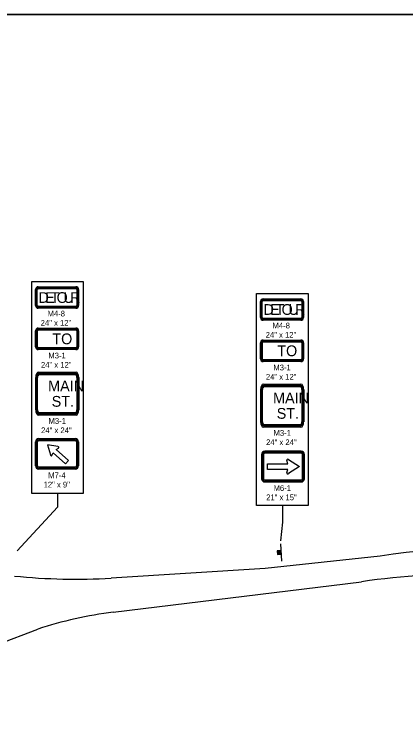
# Model space of a CAD drawing. Extents: x 10133 to 81668, y 6132 to 11018.
# Drawn here: x 10970 to 11517, y 8934 to 9944 of the extents above; entities that cross this region are included whole.
import ezdxf

# ---------------------------------------------------------------- set-up
doc = ezdxf.new("R2010")
doc.units = 0
for name, color, linetype in [('dsnTextFinalPlan', 7, 'Continuous'), ('Level 10', 7, 'Continuous'), ('Level 5', 7, 'Continuous'), ('SheetBorder', 7, 'Continuous'), ('SheetText', 7, 'Continuous')]:
    doc.layers.add(name, color=color, linetype=linetype)

msp = doc.modelspace()

# ---------------------------------------------------------------- linework, layer by layer
at = {"layer": 'dsnTextFinalPlan'}
for p, q in [((10999.7, 9313.4), (10999.7, 9347.2)), ((11004.3, 9351.7), (11055.3, 9351.7)), ((11059.8, 9347.2), (11059.8, 9313.4)), ((11055.3, 9308.8), (11004.3, 9308.8)), ((11342.2, 9204.5), (11343.8, 9180.6)), ((11338.2, 9194.7), (11338.5, 9189.8)), ((11338.8, 9189.9), (11338.5, 9194.7)), ((11338.7, 9194.7), (11339, 9189.9)), ((11339.3, 9189.9), (11338.9, 9194.8)), ((11339.1, 9194.8), (11339.5, 9189.9)), ((11339.8, 9189.9), (11339.5, 9194.8)), ((11339.7, 9194.8), (11340, 9190)), ((11340.4, 9190), (11340.1, 9194.8)), ((11340.4, 9194.9), (11340.7, 9190)), ((11341, 9190), (11340.7, 9194.9)), ((11340.9, 9194.9), (11341.2, 9190)), ((11341.4, 9190.1), (11341.1, 9194.9)), ((11341.4, 9194.9), (11341.7, 9190.1)), ((11341.9, 9190.1), (11341.6, 9194.9)), ((11341.8, 9195), (11342.1, 9190.1)), ((11342.3, 9190.1), (11342, 9195)), ((11342.2, 9195), (11342.6, 9190.1)), ((11342.8, 9190.1), (11342.5, 9195)), ((11108.6, 9109), (11455.8, 9151.7)), ((10879.5, 9038.3), (11002.9, 9085.5))]:
    msp.add_line(p, q, dxfattribs=at)
for points in [[(10994.4, 9571.2), (11066.4, 9571.2), (11066.4, 9275.1), (10994.4, 9275.1)], [(10994.4, 9571.2), (11066.4, 9571.2), (11066.4, 9275.1), (10994.4, 9275.1)], [(11309, 9554.4), (11381.1, 9554.4), (11381.1, 9258.3), (11309, 9258.3)], [(11309, 9554.4), (11381.1, 9554.4), (11381.1, 9258.3), (11309, 9258.3)], [(11343.1, 9190.2), (11342.7, 9195.1), (11337.8, 9194.7), (11338.2, 9189.8)]]:
    msp.add_lwpolyline(points, close=True, dxfattribs=at)
for points in [[(11031, 9340.6), (11016.6, 9342.7), (11020.5, 9328.7)], [(11022.7, 9328.2), (11024.3, 9331.7), (11041.7, 9316.4), (11045.8, 9321.1), (11028.5, 9336.4), (11031.8, 9338.4)], [(11030.4, 9275.1), (11030.4, 9255.6), (10974.1, 9194.9)], [(11345, 9258.3), (11345, 9234.7), (11342.4, 9208.7)], [(11481.7, 9187.4), (11321, 9170), (11105.8, 9156.6)]]:
    msp.add_lwpolyline(points, dxfattribs=at)
for centre, radius, start, end in [((11004.3, 9347.2), 4.58, 90, 180), ((11055.3, 9347.2), 4.58, 0, 90), ((11047.5, 9455.4), 116, 261.8049, 261.9654), ((11031.2, 9339.4), 1.16, 302.6073, 81.9654), ((10908.7, 9297.8), 116, 15.2659, 15.4333), ((11021.7, 9328.7), 1.14, 195.2659, 334.5454), ((11004.3, 9313.4), 4.58, 180, 270), ((11055.3, 9313.4), 4.58, 270, 0), ((11625.5, 8266), 932.6, 80.7356, 98.8682), ((11618.9, 7976.3), 1186.7, 81.0032, 97.8988), ((11056.8, 10017.6), 862.4, 264.2445, 273.255), ((11172.1, 8574), 538.7, 96.7772, 108.3032)]:
    msp.add_arc(centre, radius, start, end, dxfattribs=at)
at = {"layer": 'Level 10'}
for p, q in [((10999.8, 9537.4), (10999.8, 9559.9)), ((11000.7, 9559.9), (11002.3, 9559.9)), ((11003.6, 9563.7), (11056.2, 9563.7)), ((11003.6, 9561.2), (11003.6, 9562.7)), ((11056.2, 9562.7), (11056.2, 9561.2)), ((11057.4, 9559.9), (11059, 9559.9)), ((11059.9, 9559.9), (11059.9, 9537.4)), ((11318.2, 9546.9), (11370.8, 9546.9)), ((11318.2, 9544.4), (11318.2, 9546)), ((11370.8, 9546), (11370.8, 9544.4)), ((11002.3, 9537.4), (11000.7, 9537.4)), ((11003.6, 9534.5), (11003.6, 9536.1)), ((11056.2, 9536.1), (11056.2, 9534.5)), ((11059, 9537.4), (11057.4, 9537.4)), ((11314.4, 9520.6), (11314.4, 9543.1)), ((11315.4, 9543.1), (11316.9, 9543.1)), ((11372.1, 9543.1), (11373.6, 9543.1)), ((11374.6, 9543.1), (11374.6, 9520.6)), ((11056.2, 9533.6), (11003.6, 9533.6)), ((11316.9, 9520.6), (11315.4, 9520.6)), ((11318.2, 9517.8), (11318.2, 9519.3)), ((11370.8, 9516.8), (11318.2, 9516.8)), ((11370.8, 9519.3), (11370.8, 9517.8)), ((11373.6, 9520.6), (11372.1, 9520.6)), ((11003.6, 9506), (11056.2, 9506)), ((11003.6, 9503.5), (11003.6, 9505)), ((11056.2, 9505), (11056.2, 9503.5)), ((10999.8, 9479.7), (10999.8, 9502.2)), ((11000.8, 9502.2), (11002.4, 9502.2)), ((11057.5, 9502.2), (11059, 9502.2)), ((11060, 9502.2), (11060, 9479.7)), ((11314.5, 9462.9), (11314.5, 9485.5)), ((11315.4, 9485.5), (11317, 9485.5)), ((11318.2, 9489.2), (11370.9, 9489.2)), ((11318.2, 9486.7), (11318.2, 9488.3)), ((11370.9, 9488.3), (11370.9, 9486.7)), ((11372.1, 9485.5), (11373.7, 9485.5)), ((11374.6, 9485.5), (11374.6, 9462.9)), ((11002.4, 9479.7), (11000.8, 9479.7)), ((11003.6, 9476.9), (11003.6, 9478.4)), ((11056.2, 9475.9), (11003.6, 9475.9)), ((11056.2, 9478.4), (11056.2, 9476.9)), ((11059, 9479.7), (11057.5, 9479.7)), ((11317, 9462.9), (11315.4, 9462.9)), ((11318.2, 9460.1), (11318.2, 9461.7)), ((11370.9, 9459.2), (11318.2, 9459.2)), ((11370.9, 9461.7), (11370.9, 9460.1)), ((11373.7, 9462.9), (11372.1, 9462.9)), ((11003.8, 9444.4), (11056.4, 9444.4)), ((11000, 9391.8), (11000, 9436.9)), ((11001, 9436.9), (11002.5, 9436.9)), ((11003.8, 9439.4), (11003.8, 9442.5)), ((11056.4, 9442.5), (11056.4, 9441)), ((11057.7, 9436.9), (11059.2, 9436.9)), ((11060.2, 9436.9), (11060.2, 9391.8)), ((11318.4, 9427.6), (11371, 9427.6)), ((11318.4, 9422.6), (11318.4, 9425.8)), ((11371, 9425.8), (11371, 9424.2)), ((11314.7, 9375), (11314.7, 9420.1)), ((11315.6, 9420.1), (11317.2, 9420.1)), ((11372.3, 9420.1), (11373.9, 9420.1)), ((11374.8, 9420.1), (11374.8, 9375)), ((11002.5, 9391.8), (11001, 9391.8)), ((11003.8, 9386.1), (11003.8, 9389.3)), ((11056.4, 9384.3), (11003.8, 9384.3)), ((11056.4, 9387.7), (11056.4, 9386.1)), ((11059.2, 9391.8), (11057.7, 9391.8)), ((11317.2, 9375), (11315.6, 9375)), ((11373.9, 9375), (11372.3, 9375)), ((11318.4, 9369.4), (11318.4, 9372.5)), ((11371, 9367.5), (11318.4, 9367.5)), ((11371, 9370.9), (11371, 9369.4)), ((11000.9, 9313.4), (11000.9, 9347.2)), ((11002.6, 9313.4), (11002.6, 9347.2)), ((11004.3, 9350.6), (11055.3, 9350.6)), ((11004.3, 9348.9), (11055.3, 9348.9)), ((11057, 9347.2), (11057, 9313.4)), ((11058.7, 9347.2), (11058.7, 9313.4)), ((11371.3, 9334), (11320.4, 9334)), ((11371.3, 9332.8), (11320.4, 9332.8)), ((11315.8, 9329.4), (11315.8, 9295.6)), ((11316.9, 9329.4), (11316.9, 9295.6)), ((11318.6, 9329.4), (11318.6, 9295.6)), ((11371.3, 9331.1), (11320.4, 9331.1)), ((11373, 9295.6), (11373, 9329.4)), ((11374.8, 9295.6), (11374.8, 9329.4)), ((11375.9, 9295.6), (11375.9, 9329.4)), ((11055.3, 9311.6), (11004.3, 9311.6)), ((11055.3, 9309.9), (11004.3, 9309.9)), ((11320.4, 9293.9), (11371.3, 9293.9)), ((11320.4, 9292.2), (11371.3, 9292.2)), ((11320.4, 9291), (11371.3, 9291))]:
    msp.add_line(p, q, dxfattribs=at)
for points in [[(11000.7, 9559.9), (11000.7, 9537.4), (11002.3, 9537.4), (11002.3, 9559.9), (11000.7, 9559.9)], [(11056.2, 9562.7), (11003.6, 9562.7), (11003.6, 9561.2), (11056.2, 9561.2), (11056.2, 9562.7)], [(11059, 9537.4), (11059, 9559.9), (11057.4, 9559.9), (11057.4, 9537.4), (11059, 9537.4)], [(11370.8, 9546), (11318.2, 9546), (11318.2, 9544.4), (11370.8, 9544.4), (11370.8, 9546)], [(11003.6, 9534.5), (11056.2, 9534.5), (11056.2, 9536.1), (11003.6, 9536.1), (11003.6, 9534.5)], [(11315.4, 9543.1), (11315.4, 9520.6), (11316.9, 9520.6), (11316.9, 9543.1), (11315.4, 9543.1)], [(11373.6, 9520.6), (11373.6, 9543.1), (11372.1, 9543.1), (11372.1, 9520.6), (11373.6, 9520.6)], [(11318.2, 9517.8), (11370.8, 9517.8), (11370.8, 9519.3), (11318.2, 9519.3), (11318.2, 9517.8)], [(11056.2, 9505), (11003.6, 9505), (11003.6, 9503.5), (11056.2, 9503.5), (11056.2, 9505)], [(11000.8, 9502.2), (11000.8, 9479.7), (11002.4, 9479.7), (11002.4, 9502.2), (11000.8, 9502.2)], [(11059, 9479.7), (11059, 9502.2), (11057.5, 9502.2), (11057.5, 9479.7), (11059, 9479.7)], [(11315.4, 9485.5), (11315.4, 9462.9), (11317, 9462.9), (11317, 9485.5), (11315.4, 9485.5)], [(11370.9, 9488.3), (11318.2, 9488.3), (11318.2, 9486.7), (11370.9, 9486.7), (11370.9, 9488.3)], [(11373.7, 9462.9), (11373.7, 9485.5), (11372.1, 9485.5), (11372.1, 9462.9), (11373.7, 9462.9)], [(11003.6, 9476.9), (11056.2, 9476.9), (11056.2, 9478.4), (11003.6, 9478.4), (11003.6, 9476.9)], [(11318.2, 9460.1), (11370.9, 9460.1), (11370.9, 9461.7), (11318.2, 9461.7), (11318.2, 9460.1)], [(11001, 9436.9), (11001, 9391.8), (11002.5, 9391.8), (11002.5, 9436.9), (11001, 9436.9)], [(11056.4, 9442.5), (11003.8, 9442.5), (11003.8, 9441), (11056.4, 9441), (11056.4, 9442.5)], [(11059.2, 9391.8), (11059.2, 9436.9), (11057.7, 9436.9), (11057.7, 9391.8), (11059.2, 9391.8)], [(11371, 9425.8), (11318.4, 9425.8), (11318.4, 9424.2), (11371, 9424.2), (11371, 9425.8)], [(11315.6, 9420.1), (11315.6, 9375), (11317.2, 9375), (11317.2, 9420.1), (11315.6, 9420.1)], [(11373.9, 9375), (11373.9, 9420.1), (11372.3, 9420.1), (11372.3, 9375), (11373.9, 9375)], [(11003.8, 9386.1), (11056.4, 9386.1), (11056.4, 9387.7), (11003.8, 9387.7), (11003.8, 9386.1)], [(11318.4, 9369.4), (11371, 9369.4), (11371, 9370.9), (11318.4, 9370.9), (11318.4, 9369.4)]]:
    msp.add_lwpolyline(points, close=True, dxfattribs=at)
for points in [[(11353.8, 9322.3), (11368.8, 9312.5), (11353.8, 9302.7)], [(11351.3, 9304), (11352.7, 9308.6), (11324.1, 9308.6), (11324.1, 9316.4), (11352.7, 9316.4), (11351.3, 9321)]]:
    msp.add_lwpolyline(points, dxfattribs=at)
for centre, radius, start, end in [((11003.6, 9559.9), 3.76, 90, 180), ((11003.6, 9559.9), 2.82, 90.0002, 179.9998), ((11003.6, 9559.9), 1.25, 90.0002, 179.9998), ((11056.2, 9559.9), 3.76, 0, 90), ((11056.2, 9559.9), 2.82, 0, 90.0002), ((11056.2, 9559.9), 1.25, 0, 90.0002), ((11318.2, 9543.1), 3.76, 90, 180), ((11318.2, 9543.1), 2.82, 90.0002, 179.9998), ((11370.8, 9543.1), 3.76, 0, 90), ((11370.8, 9543.1), 2.82, 0, 90.0002), ((11003.6, 9537.4), 3.76, 180, 270), ((11003.6, 9537.4), 2.82, 179.9998, 270.0001), ((11003.6, 9537.4), 1.25, 179.9998, 270.0001), ((11056.2, 9537.4), 2.82, 270.0001, 0.0003), ((11056.2, 9537.4), 1.25, 270.0001, 0.0003), ((11056.2, 9537.4), 3.76, 270, 359.9911), ((11318.2, 9543.1), 1.25, 90.0002, 179.9998), ((11370.8, 9543.1), 1.25, 0, 90.0002), ((11318.2, 9520.6), 3.76, 180, 270), ((11318.2, 9520.6), 2.82, 179.9998, 270.0001), ((11318.2, 9520.6), 1.25, 179.9998, 270.0001), ((11370.8, 9520.6), 2.82, 270.0001, 0.0003), ((11370.8, 9520.6), 1.25, 270.0001, 0.0003), ((11370.8, 9520.6), 3.76, 270, 359.9911), ((11003.6, 9502.2), 3.76, 90, 180), ((11003.6, 9502.2), 2.82, 90.0002, 179.9998), ((11056.2, 9502.2), 3.76, 0, 90), ((11056.2, 9502.2), 2.82, 0, 90.0002), ((11003.6, 9502.2), 1.25, 90.0002, 179.9998), ((11056.2, 9502.2), 1.25, 0, 90.0002), ((11318.2, 9485.5), 3.76, 90, 180), ((11318.2, 9485.5), 2.82, 90.0002, 179.9998), ((11318.2, 9485.5), 1.25, 90.0002, 179.9998), ((11370.9, 9485.5), 3.76, 0, 90), ((11370.9, 9485.5), 2.82, 0, 90.0002), ((11370.9, 9485.5), 1.25, 0, 90.0002), ((11003.6, 9479.7), 3.76, 180, 270), ((11003.6, 9479.7), 2.82, 179.9998, 270.0001), ((11003.6, 9479.7), 1.25, 179.9998, 270.0001), ((11056.2, 9479.7), 2.82, 270.0001, 0.0003), ((11056.2, 9479.7), 1.25, 270.0001, 0.0003), ((11056.2, 9479.7), 3.76, 270, 359.9911), ((11318.2, 9462.9), 3.76, 180, 270), ((11318.2, 9462.9), 2.82, 179.9998, 270.0001), ((11318.2, 9462.9), 1.25, 179.9998, 270.0001), ((11370.9, 9462.9), 2.82, 270.0001, 0.0003), ((11370.9, 9462.9), 1.25, 270.0001, 0.0003), ((11370.9, 9462.9), 3.76, 270, 359.9911), ((11004.3, 9347.2), 3.44, 90, 180), ((11004.3, 9347.2), 1.72, 90, 180), ((11055.3, 9347.2), 3.44, 0, 90), ((11055.3, 9347.2), 1.72, 0, 90), ((11320.4, 9329.4), 4.58, 90, 180), ((11320.4, 9329.4), 3.44, 90, 180), ((11371.3, 9329.4), 4.58, 360, 90), ((11371.3, 9329.4), 3.44, 0, 90), ((11320.4, 9329.4), 1.72, 90, 180), ((11352.6, 9321.3), 1.43, 56.6109, 195.9691), ((11432.2, 9442.1), 143.2, 236.6109, 236.7714), ((11371.3, 9329.4), 1.72, 0, 90), ((11004.3, 9313.4), 3.44, 180, 270), ((11004.3, 9313.4), 1.72, 180, 270), ((11055.3, 9313.4), 3.44, 270, 0), ((11055.3, 9313.4), 1.72, 270, 0), ((11352.6, 9303.7), 1.4, 164.0309, 303.3104), ((11432, 9182.8), 143.2, 123.143, 123.3104), ((11320.4, 9295.6), 4.58, 180, 270), ((11320.4, 9295.6), 3.44, 180, 270), ((11320.4, 9295.6), 1.72, 180, 270), ((11371.3, 9295.6), 4.58, 270, 0), ((11371.3, 9295.6), 3.44, 270, 360), ((11371.3, 9295.6), 1.72, 270, 0)]:
    msp.add_arc(centre, radius, start, end, dxfattribs=at)
for centre, major_axis, ratio, start_param, end_param in [((11003.8, 9436.9), (0, 7.52), 0.5, 6.283185, 7.853982), ((11056.4, 9436.9), (0, 7.52), 0.5, 4.712389, 6.283185), ((11003.8, 9436.9), (0, 5.64), 0.5, 0.000004, 1.570794), ((11003.8, 9436.9), (0, 4.07), 0.307692, 0.000004, 1.570794), ((11056.4, 9436.9), (0, 5.64), 0.5, 4.712389, 6.283189), ((11056.4, 9436.9), (0, 4.07), 0.307692, 4.712389, 6.283189), ((11318.4, 9420.1), (0, 7.52), 0.5, 6.283185, 7.853982), ((11318.4, 9420.1), (0, 5.64), 0.5, 0.000004, 1.570794), ((11318.4, 9420.1), (0, 4.07), 0.307692, 0.000004, 1.570794), ((11371, 9420.1), (0, 7.52), 0.5, 4.712389, 6.283185), ((11371, 9420.1), (0, 5.64), 0.5, 4.712389, 6.283189), ((11371, 9420.1), (0, 4.07), 0.307692, 4.712389, 6.283189), ((11003.8, 9391.8), (0, 7.52), 0.5, 1.570796, 3.141593), ((11003.8, 9391.8), (0, 5.64), 0.5, 1.570794, 3.141594), ((11003.8, 9391.8), (0, 4.07), 0.307692, 1.570794, 3.141594), ((11056.4, 9391.8), (0, 5.64), 0.5, 3.141594, 4.712394), ((11056.4, 9391.8), (0, 4.07), 0.307692, 3.141594, 4.712394), ((11056.4, 9391.8), (0, 7.52), 0.5, 3.141593, 4.712234), ((11318.4, 9375), (0, 7.52), 0.5, 1.570796, 3.141593), ((11318.4, 9375), (0, 5.64), 0.5, 1.570794, 3.141594), ((11318.4, 9375), (0, 4.07), 0.307692, 1.570794, 3.141594), ((11371, 9375), (0, 5.64), 0.5, 3.141594, 4.712394), ((11371, 9375), (0, 4.07), 0.307692, 3.141594, 4.712394), ((11371, 9375), (0, 7.52), 0.5, 3.141593, 4.712234)]:
    msp.add_ellipse(centre, major_axis=major_axis, ratio=ratio, start_param=start_param, end_param=end_param, dxfattribs=at)
at = {"layer": 'SheetBorder'}
msp.add_lwpolyline([(10132.5, 9944), (13267.5, 9944), (13267.5, 7924), (10132.5, 7924)], close=True, dxfattribs=at)
at = {"layer": 'SheetText'}
msp.add_lwpolyline([(10132.5, 9944), (10132.5, 7924), (13267.5, 7924), (13267.5, 9944)], close=True, dxfattribs=at)

# ---------------------------------------------------------------- texts
at = {"layer": 'Level 10'}
for s, height, p in [('D', 15, (11004, 9541.1)), ('E', 15, (11013.3, 9541.1)), ('T', 15, (11021.1, 9541.1)), ('O', 15, (11029.3, 9541.1)), ('U', 15, (11038.9, 9541.1)), ('R', 15, (11048.1, 9541.1)), ('D', 15, (11318.7, 9524.4)), ('E', 15, (11327.9, 9524.4)), ('T', 15, (11335.7, 9524.4)), ('O', 15, (11343.9, 9524.4)), ('U', 15, (11353.5, 9524.4)), ('R', 15, (11362.7, 9524.4)), ('TO', 15.03, (11023.3, 9483.4)), ('TO', 15.03, (11337.9, 9466.7)), ('MAIN', 15.03, (11017.4, 9417.6)), ('MAIN', 15.03, (11332, 9400.8)), ('ST.', 15.03, (11022.4, 9396.1)), ('ST.', 15.03, (11337.1, 9379.3))]:
    msp.add_text(s, height=height, dxfattribs=at).set_placement(p)
at = {"layer": 'Level 5'}
for s, p in [('M4-8', (11016.6, 9522.2)), ('24" x 12"', (11007, 9509.2)), ('M4-8', (11331.2, 9505.5)), ('24" x 12"', (11321.7, 9492.5)), ('M3-1', (11017.7, 9463.6)), ('24" x 12"', (11007.4, 9450.6)), ('M3-1', (11332.4, 9446.9)), ('24" x 12"', (11322, 9433.9)), ('M3-1', (11017.9, 9372.2)), ('24" x 24"', (11007.6, 9359.2)), ('M3-1', (11332.6, 9355.5)), ('24" x 24"', (11322.2, 9342.5)), ('M7-4', (11017.5, 9296.3)), ('12" x 9"', (11011.1, 9283.3)), ('M6-1', (11332.7, 9278.5)), ('21" x 15"', (11322.4, 9265.5))]:
    msp.add_text(s, height=8, dxfattribs=at).set_placement(p)

doc.saveas('drawing.dxf')
